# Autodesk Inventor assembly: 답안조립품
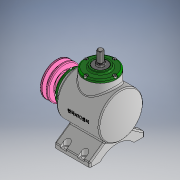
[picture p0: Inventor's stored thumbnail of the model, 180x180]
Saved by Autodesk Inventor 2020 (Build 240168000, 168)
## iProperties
Created: 2023-12
Part Number: 답안조립품
Document SubType Name: Assembly
Designer: 1강의실14
Author: 1강의실14
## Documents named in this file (17)
- C:\Users\1강의실14\Desktop\731203V1010\731203V1010\답안조립품.iam
- C:\Users\1강의실14\Desktop\731203V1010\731203V1010\본체.ipt
- C:\Users\1강의실14\Desktop\731203V1010\731203V1010\V-벨트풀리.ipt
- C:\Users\1강의실14\Desktop\731203V1010\731203V1010\메인 베벨기어.ipt
- C:\Users\1강의실14\Desktop\731203V1010\731203V1010\메인 축.ipt
- 메인 축.ipt
- C:\Users\1강의실14\Desktop\731203V1010\731203V1010\베어링 6203.ipt
- C:\Users\1강의실14\Desktop\731203V1010\731203V1010\볼트 M4 x 10.ipt
- C:\Users\1강의실14\Desktop\731203V1010\731203V1010\서브 베벨기어.ipt
- C:\Users\1강의실14\Desktop\731203V1010\731203V1010\서브 축.ipt
- 서브 축.ipt
- C:\Users\1강의실14\Desktop\731203V1010\731203V1010\오일실 17 x 32 x 8.ipt
- C:\Users\1강의실14\Desktop\731203V1010\731203V1010\와셔 4 x 16.ipt
- C:\Users\1강의실14\Desktop\731203V1010\731203V1010\육각볼트 M4 x 8.ipt
- C:\Users\1강의실14\Desktop\731203V1010\731203V1010\커버.ipt
- C:\Users\1강의실14\Desktop\731203V1010\731203V1010\키 4 x 4 x 14.ipt
- C:\Users\1강의실14\Desktop\731203V1010\731203V1010\키 5 x 5 x 14.ipt
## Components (1 placed, 1 different names)
1. V-벨트풀리:1
